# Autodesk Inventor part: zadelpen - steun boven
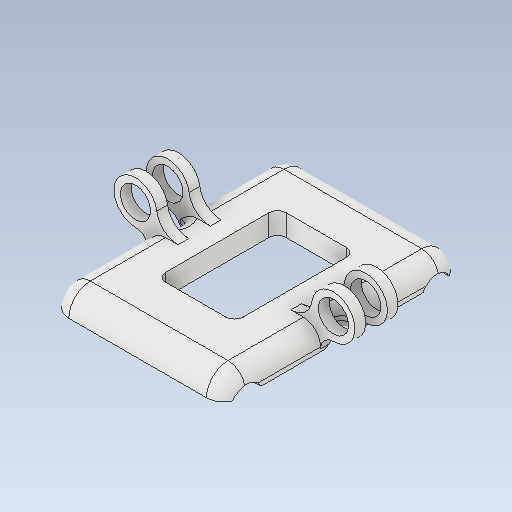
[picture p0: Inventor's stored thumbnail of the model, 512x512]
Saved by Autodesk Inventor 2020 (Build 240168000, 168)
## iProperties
Created: 2017-11
Part Number: zadelpen - steun boven
Material: Ogólny
Document SubType Name: Modeling
Designer: Tomasz
Density: 1 g/cm^3
Appearance: Domyślna
Author: Tomasz
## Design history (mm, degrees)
feature "Solid1"
node "Bryła1"
